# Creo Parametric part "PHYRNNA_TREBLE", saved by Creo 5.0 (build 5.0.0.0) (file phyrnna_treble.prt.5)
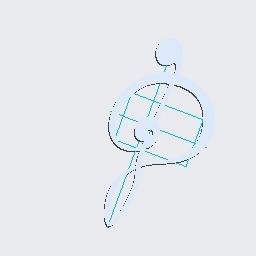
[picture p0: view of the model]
Units: Inch lbm Second (Pro/E Default); INCH, POUND, SECS

Created from: INLBS_PART_SOLID.PRT

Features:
  1. datum plane "RIGHT"
  2. datum plane "TOP"
  3. datum plane "FRONT"
  4. coordinate system
  5. sketch "Sketch 1"
  6. sketch "Sketch 2"
  7. extrusion "Extrude 1"

Other named items: REFERENCE, TREBLE_S, TREBLE_E

Surfaces: 18 tabulated cylinder, 2 plane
